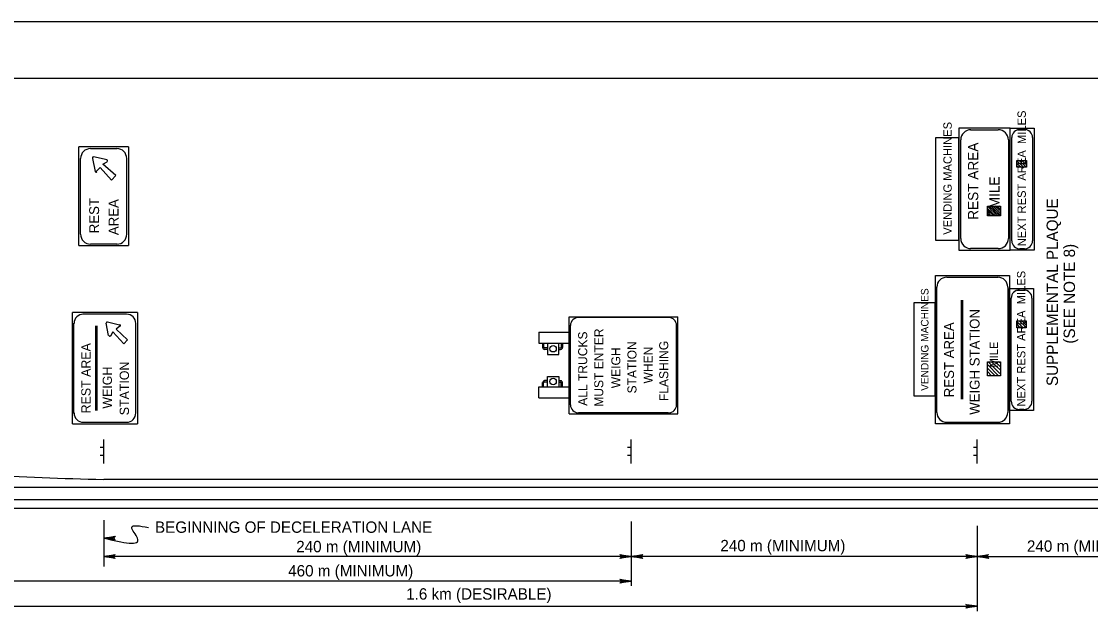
# Model space of a CAD drawing. Extents: x 649604 to 650509, y 298458 to 299646.
# Drawn here: x 649924.8 to 650206.9, y 299489.7 to 299645.6 of the extents above; entities that cross this region are included whole.
import ezdxf

# ---------------------------------------------------------------- set-up
doc = ezdxf.new("R2010")
doc.units = 0
for name, color, linetype in [('1', 7, 'Continuous'), ('2', 7, 'Continuous'), ('3', 7, 'Continuous'), ('PLT-BNDY', 7, 'Continuous')]:
    doc.layers.add(name, color=color, linetype=linetype)

# ---------------------------------------------------------------- blocks, each defined once
blk = doc.blocks.new('RARROW')
at = {"layer": '3'}
blk.add_lwpolyline([(-2.2695, 0.285), (-2.184875, 0.12075), (0, 0), (-2.2695, 0.285), (-2.38575, 0.384625), (0, 0), (-2.183125, -0.108), (-2.262875, -0.2705), (0, 0), (-2.38575, -0.379125), (-2.262875, -0.2705)], dxfattribs=at)

msp = doc.modelspace()

# ---------------------------------------------------------------- linework, layer by layer
at = {"layer": '1'}
msp.add_line((649644.31, 299630.63), (650430.31, 299630.63), dxfattribs=at)
at = {"layer": '2'}
for p, q in [((650175.18, 299617.06), (650182.47, 299617.06)), ((650188.21, 299617.13), (650189.38, 299617.13)), ((650186.05, 299587.79), (650186.05, 299614.97)), ((650191.54, 299614.97), (650191.54, 299587.79)), ((649939.94, 299586.5), (649939.94, 299612.5)), ((649953.06, 299612.5), (649939.94, 299612.5)), ((649943.06, 299612.13), (649950.06, 299612.13)), ((649953.06, 299612.5), (649953.06, 299586.5)), ((649940.44, 299589.5), (649940.44, 299609.5)), ((649943.56, 299609.5), (649944.31, 299606)), ((649947.44, 299609.13), (649943.81, 299609.88)), ((649946.31, 299608), (649947.44, 299608.63)), ((649952.56, 299609.5), (649952.56, 299589.5)), ((650189.15, 299607.14), (650187.41, 299608.88)), ((650188.45, 299607.14), (650187.41, 299608.18)), ((650189.86, 299607.14), (650188.04, 299608.96)), ((650189.94, 299607.77), (650188.74, 299608.96)), ((650189.94, 299608.47), (650189.45, 299608.96)), ((649944.56, 299606), (649945.56, 299607.13)), ((649945.56, 299607.13), (649948.56, 299603.75)), ((649949.69, 299605), (649946.31, 299608)), ((650187.74, 299607.14), (650187.41, 299607.47)), ((649948.56, 299603.75), (649949.69, 299605)), ((649939.94, 299586.5), (649953.06, 299586.5)), ((649950.06, 299586.88), (649943.06, 299586.88)), ((650189.38, 299585.63), (650188.21, 299585.63)), ((650165.94, 299539.5), (650165.94, 299578.63)), ((650168.94, 299578.13), (650182.44, 299578.13)), ((650185.44, 299578.63), (650185.44, 299539.5)), ((650166.31, 299542.5), (650166.31, 299575.63)), ((650185.06, 299575.63), (650185.06, 299542.5)), ((650188.06, 299574.78), (650189.23, 299574.78)), ((650172.81, 299546), (650172.81, 299572.13)), ((650172.81, 299546), (650172.81, 299572.13)), ((650172.94, 299546), (650172.94, 299572.13)), ((650173.06, 299546), (650173.06, 299572.13)), ((650173.19, 299546), (650173.19, 299572.13)), ((650185.9, 299545.45), (650185.9, 299572.63)), ((650191.39, 299572.63), (650191.39, 299545.45)), ((649938.31, 299539.5), (649938.31, 299568.88)), ((649955.44, 299568.88), (649938.31, 299568.88)), ((649955.44, 299568.88), (649955.44, 299539.5)), ((649938.69, 299542.25), (649938.69, 299566)), ((649941.06, 299568.5), (649952.56, 299568.5)), ((649947.81, 299562.75), (649947.19, 299566)), ((649947.56, 299566.38), (649950.69, 299565.63)), ((649954.94, 299566), (649954.94, 299542.25)), ((650069.31, 299542.13), (650069.31, 299567.75)), ((650069.31, 299567.75), (650097.94, 299567.75)), ((650071.81, 299567.63), (650095.44, 299567.63)), ((650097.94, 299542.13), (650097.94, 299567.75)), ((650189.05, 299564.83), (650187.35, 299566.52)), ((650188.31, 299564.83), (650187.35, 299565.79)), ((650189.83, 299564.86), (650188.04, 299566.65)), ((650189.88, 299565.52), (650188.75, 299566.65)), ((650189.88, 299566.22), (650189.46, 299566.65)), ((649944.44, 299543), (649944.44, 299565.38)), ((649944.44, 299543), (649944.44, 299565.38)), ((649944.56, 299543), (649944.56, 299565.38)), ((649944.69, 299543), (649944.69, 299565.38)), ((649944.81, 299543), (649944.81, 299565.38)), ((649948.94, 299563.75), (649948.31, 299562.63)), ((649951.81, 299560.63), (649948.94, 299563.75)), ((649950.81, 299565.25), (649949.81, 299564.5)), ((649949.81, 299564.5), (649952.81, 299561.63)), ((650061.31, 299563.63), (650061.31, 299560.75)), ((650061.31, 299563.63), (650069.31, 299563.63)), ((650069.69, 299544.5), (650069.69, 299565.5)), ((650097.56, 299565.5), (650097.56, 299544.5)), ((650187.6, 299564.83), (650187.35, 299565.08)), ((649952.81, 299561.63), (649951.81, 299560.63)), ((650061.31, 299560.75), (650063.56, 299560.75)), ((650062.31, 299560.75), (650062.31, 299559.63)), ((650062.56, 299560.75), (650062.56, 299559.63)), ((650063.56, 299560.75), (650063.56, 299557.75)), ((650063.56, 299560.75), (650069.31, 299560.75)), ((650066.56, 299557.75), (650066.56, 299560.75)), ((650067.19, 299560.75), (650067.19, 299559.63)), ((650067.56, 299560.75), (650067.56, 299559.63)), ((650063.56, 299559.5), (650062.81, 299559.5)), ((650063.56, 299559.13), (650062.81, 299559.13)), ((650063.56, 299557.75), (650066.56, 299557.75)), ((650066.56, 299559.5), (650067.06, 299559.5)), ((650066.56, 299559.13), (650067.06, 299559.13)), ((650063.56, 299549.25), (650063.56, 299552)), ((650063.56, 299552), (650066.56, 299552)), ((650066.56, 299552), (650066.56, 299549.25)), ((650061.31, 299546.38), (650061.31, 299549.25)), ((650061.31, 299549.25), (650063.56, 299549.25)), ((650062.31, 299549.25), (650062.31, 299550.38)), ((650062.56, 299549.25), (650062.56, 299550.38)), ((650063.56, 299550.88), (650062.81, 299550.88)), ((650063.56, 299550.5), (650062.81, 299550.5)), ((650063.56, 299549.25), (650069.31, 299549.25)), ((650066.56, 299550.88), (650067.06, 299550.88)), ((650066.56, 299550.5), (650067.06, 299550.5)), ((650067.19, 299549.25), (650067.19, 299550.38)), ((650067.56, 299549.25), (650067.56, 299550.38)), ((650061.31, 299546.38), (650069.31, 299546.38)), ((650189.23, 299543.29), (650188.06, 299543.29)), ((650069.31, 299542.13), (650097.94, 299542.13)), ((650095.44, 299542.38), (650071.81, 299542.38)), ((649938.31, 299539.5), (649955.44, 299539.5)), ((649952.56, 299539.88), (649941.06, 299539.88)), ((649946.56, 299529), (649946.56, 299535.38)), ((650085.69, 299529), (650085.69, 299535.38)), ((650176.94, 299529), (650176.94, 299535.38)), ((649946.56, 299533.25), (649945.56, 299533.25)), ((650085.69, 299533.25), (650084.69, 299533.25)), ((650176.94, 299533.25), (650175.94, 299533.25)), ((649946.56, 299531.13), (649945.56, 299531.13)), ((650085.69, 299531.13), (650084.69, 299531.13)), ((650176.94, 299531.13), (650175.94, 299531.13)), ((649946.56, 299524.88), (650390.69, 299524.88)), ((649664.19, 299522.75), (650390.69, 299522.75)), ((649664.19, 299519.5), (650390.69, 299519.5)), ((649664.19, 299517.25), (650390.69, 299517.25)), ((649946.56, 299514.13), (649946.56, 299501.88)), ((650085.69, 299513.75), (650085.69, 299496.75)), ((650176.94, 299512.63), (650176.94, 299490.13)), ((650176.94, 299504.5), (649946.56, 299504.5)), ((650176.94, 299504.5), (650244.31, 299504.5)), ((650085.69, 299498), (649881.31, 299498)), ((649881.31, 299491.38), (650176.94, 299491.38))]:
    msp.add_line(p, q, dxfattribs=at)
for points in [[(650185.59, 299585.32), (650185.59, 299617.49), (650172.11, 299617.49), (650172.11, 299585.32)], [(650185.59, 299617.49), (650191.98, 299617.49), (650191.98, 299585.32), (650185.59, 299585.32)], [(650172.11, 299587.92), (650172.11, 299614.88), (650165.92, 299614.88), (650165.92, 299587.92)], [(650189.94, 299607.14), (650187.41, 299607.14), (650187.41, 299608.96), (650189.94, 299608.96)], [(650183.11, 299594.39), (650179.67, 299594.39), (650179.67, 299596.87), (650183.11, 299596.87)], [(650185.44, 299575.15), (650191.83, 299575.15), (650191.83, 299542.98), (650185.44, 299542.98)], [(650165.81, 299546.86), (650165.81, 299571.38), (650160.19, 299571.38), (650160.19, 299546.86)], [(650189.88, 299564.83), (650187.35, 299564.83), (650187.35, 299566.65), (650189.88, 299566.65)], [(650183.06, 299552.13), (650179.69, 299552.13), (650179.69, 299555.88), (650183.06, 299555.88)]]:
    msp.add_lwpolyline(points, close=True, dxfattribs=at)
for points in [[(650172.61, 299588.38), (650172.61, 299614.37)], [(650185.16, 299614.37), (650185.16, 299588.38)], [(650182.29, 299594.39), (650179.67, 299596.87)], [(650182.84, 299594.39), (650180.09, 299596.87)], [(650183.11, 299594.53), (650180.64, 299596.87)], [(650183.11, 299595.08), (650181.19, 299596.87)], [(650183.11, 299595.63), (650181.6, 299596.87)], [(650183.11, 299596.04), (650182.15, 299596.87)], [(650183.11, 299596.59), (650182.7, 299596.87)], [(650181.74, 299594.39), (650179.67, 299596.32)], [(650181.32, 299594.39), (650179.67, 299595.77)], [(650180.64, 299594.39), (650179.67, 299595.36)], [(650180.36, 299594.39), (650179.67, 299594.81)], [(650182.47, 299585.7), (650175.18, 299585.7)], [(650165.94, 299578.63), (650168.31, 299578.63), (650170.81, 299578.63), (650172.94, 299578.63), (650175.06, 299578.63), (650177.56, 299578.63), (650179.69, 299578.63), (650180.44, 299578.63), (650182.56, 299578.63), (650183.06, 299578.63), (650185.44, 299578.63)], [(650166.31, 299547.25), (650166.31, 299570.88)], [(650185.06, 299571.25), (650185.06, 299547.5)], [(650185.06, 299570.88), (650185.06, 299547.25)], [(650182.56, 299552.13), (650179.69, 299555.13)], [(650182.94, 299552.75), (650179.81, 299555.88)], [(650183.06, 299553.63), (650180.69, 299555.88)], [(650183.06, 299554.5), (650181.69, 299555.88)], [(650183.06, 299555.5), (650182.56, 299555.88)], [(650181.69, 299552.13), (650179.69, 299554.13)], [(650180.69, 299552.13), (650179.69, 299553.25)], [(650179.81, 299552.13), (650179.69, 299552.25)], [(650185.44, 299539.5), (650165.94, 299539.5)], [(650182.44, 299539.88), (650168.94, 299539.88)]]:
    msp.add_lwpolyline(points, dxfattribs=at)
for centre in [(650065.07, 299559.29), (650065.07, 299550.66)]:
    msp.add_circle(centre, 0.845, dxfattribs=at)
for centre, radius, start, end in [((650175.3, 299614.37), 2.69, 90, 180), ((650182.47, 299614.37), 2.69, 0, 90), ((650188.21, 299614.97), 2.16, 90, 180), ((650189.38, 299614.97), 2.16, 0, 90), ((649943.05, 299609.46), 2.61, 90, 180), ((649950, 299609.46), 2.61, 0, 90), ((649943.76, 299609.62), 0.22, 78.2602, 191.7398), ((649947.29, 299608.88), 0.22, 303.3162, 78.2602), ((649944.5, 299606.09), 0.22, 191.7398, 326.6838), ((649943.05, 299589.48), 2.61, 180, 270), ((649950, 299589.48), 2.61, 270, 0), ((650175.3, 299588.38), 2.69, 180, 270), ((650182.47, 299588.38), 2.69, 270, 0), ((650188.21, 299587.79), 2.16, 180, 270), ((650189.38, 299587.79), 2.16, 270, 0), ((650168.91, 299575.54), 2.61, 90, 180), ((650182.39, 299575.54), 2.61, 0, 90), ((650188.06, 299572.63), 2.16, 90, 180), ((650189.23, 299572.63), 2.16, 0, 90), ((649941.15, 299565.97), 2.44, 90, 180), ((649947.42, 299566.12), 0.206, 78.2602, 191.7398), ((649952.55, 299565.97), 2.44, 0, 90), ((650071.78, 299565.42), 2.14, 90, 180), ((650095.51, 299565.42), 2.14, 0, 90), ((649950.73, 299565.43), 0.206, 303.3162, 78.2602), ((649948.11, 299562.81), 0.206, 191.7398, 326.6838), ((650062.83, 299559.65), 0.53, 180, 270), ((650062.83, 299559.65), 0.193, 180, 270), ((650067.04, 299559.65), 0.193, 270, 0), ((650067.04, 299559.65), 0.53, 270, 0), ((650062.83, 299550.3), 0.53, 90, 180), ((650062.83, 299550.3), 0.193, 90, 180), ((650067.04, 299550.3), 0.53, 0, 90), ((650067.04, 299550.3), 0.193, 0, 90), ((650071.78, 299544.53), 2.14, 180, 270), ((650095.51, 299544.53), 2.14, 270, 0), ((650188.06, 299545.45), 2.16, 180, 270), ((650189.23, 299545.45), 2.16, 270, 0), ((649941.15, 299542.35), 2.44, 180, 270), ((649952.55, 299542.35), 2.44, 270, 0), ((650168.91, 299542.5), 2.61, 180, 270), ((650182.39, 299542.5), 2.61, 270, 0), ((649975.83, 300763.06), 1238.57, 265.6447, 268.64351)]:
    msp.add_arc(centre, radius, start, end, dxfattribs=at)
msp.add_spline([(649946.56, 299509.38), (649955.44, 299509.38), (649953.94, 299512.13), (649958.31, 299512.13)], degree=3, dxfattribs=at)
at = {"layer": 'PLT-BNDY'}
msp.add_lwpolyline([(649604.31, 299645.63), (650445.31, 299645.63), (650445.31, 299051.63), (649604.31, 299051.63)], close=True, dxfattribs=at)

# ---------------------------------------------------------------- block references
at = {"layer": '2', "xscale": 1.2574347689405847, "yscale": 1.3092961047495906, "rotation": 180}
for p in [(649946.58, 299509.38), (649946.56, 299504.5), (650085.69, 299504.5), (650176.94, 299504.5)]:
    msp.add_blockref('RARROW', p, dxfattribs=at)
at = {"layer": '2', "xscale": 1.2574347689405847, "yscale": 1.3092961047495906}
for p in [(650085.69, 299504.5), (650176.94, 299504.5), (650085.69, 299498), (650176.94, 299491.38)]:
    msp.add_blockref('RARROW', p, dxfattribs=at)

# ---------------------------------------------------------------- texts
at = {"layer": '2'}
for s, height, p in [('NEXT REST AREA  MILES', 2.2, (650189.77, 299586.31)), ('VENDING MACHINES', 2.2, (650170.22, 299589.36)), ('REST AREA', 2.688, (650177.2, 299593.29)), ('    MILE', 2.687, (650182.84, 299592.33)), ('REST', 2.606, (649945.31, 299589.75)), ('AREA', 2.606, (649950.44, 299589.25)), ('SUPPLEMENTAL PLAQUE', 3, (650198.24, 299549.46)), ('(SEE NOTE 8)', 3, (650202.74, 299560.65)), ('NEXT REST AREA  MILES', 2.2, (650189.64, 299544.04)), ('VENDING MACHINES', 2, (650164.09, 299548.18)), ('WEIGH STATION', 2.6078, (650177.56, 299541.88)), ('REST AREA', 2.608, (650170.81, 299546.5)), ('ALL TRUCKS', 2.375, (650074.06, 299544.25)), ('MUST ENTER', 2.375, (650078.31, 299544)), ('REST AREA', 2.443, (649943.06, 299542.25)), ('STATION', 2.375, (650087.06, 299547.5)), ('FLASHING', 2.375, (650095.44, 299545.5)), ('  MILE', 2.174, (650182.44, 299552.75)), ('WEIGH', 2.375, (650082.81, 299548.88)), ('WHEN', 2.375, (650091.31, 299550.13)), ('STATION', 2.443, (649953.19, 299541.75)), ('WEIGH', 2.443, (649948.69, 299543.5))]:
    msp.add_text(s, height=height, rotation=90, dxfattribs=at).set_placement(p)
for s, p in [('BEGINNING OF DECELERATION LANE', (649960.06, 299510.75)), ('240 m (MINIMUM)', (649997.31, 299505.63)), ('240 m (MINIMUM)', (650109.19, 299505.88)), ('240 m (MINIMUM)', (650190.06, 299505.75)), ('460 m (MINIMUM)', (649995.19, 299499.25)), ('1.6 km (DESIRABLE)', (650026.31, 299493.13))]:
    msp.add_text(s, height=3, dxfattribs=at).set_placement(p)

doc.saveas('drawing.dxf')
